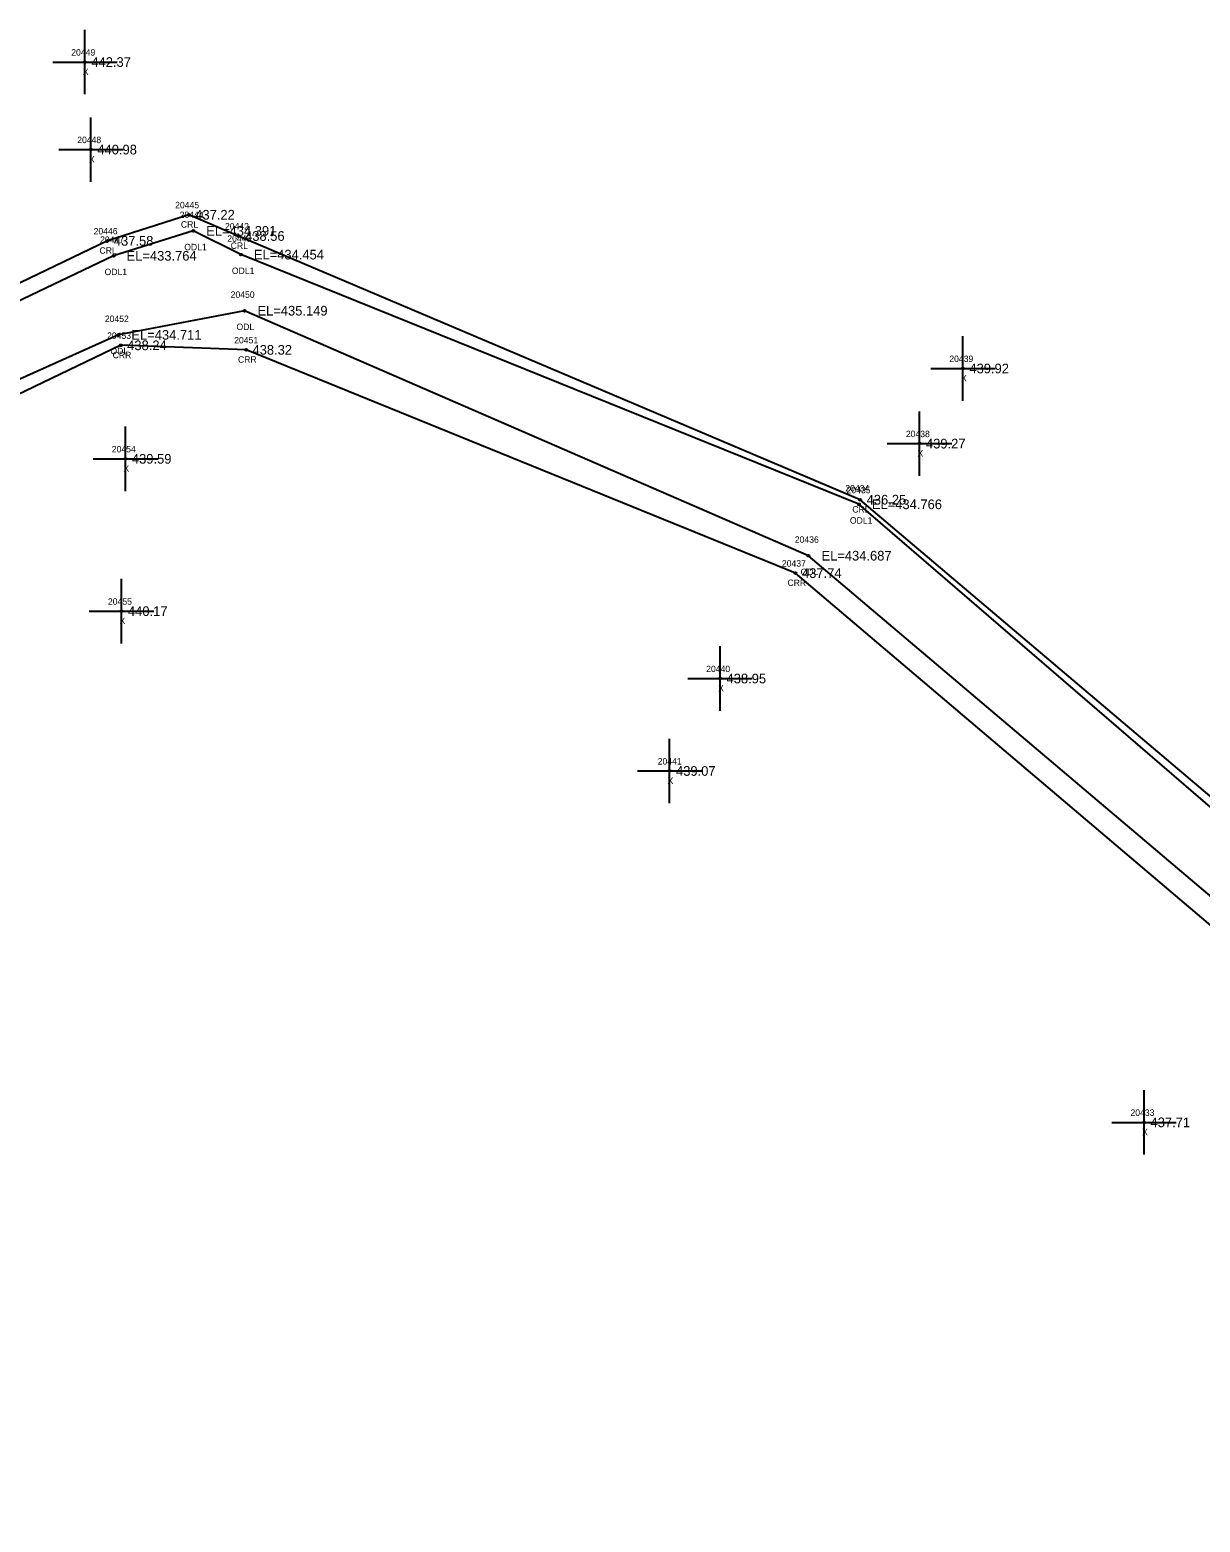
# Model space of a CAD drawing. Extents: x 1763022 to 1764007, y 824123 to 825394.
# Drawn here: x 1763194.4 to 1763375.9, y 824815.6 to 825047.2 of the extents above; entities that cross this region are included whole.
import ezdxf

# ---------------------------------------------------------------- set-up
doc = ezdxf.new("R2010")
doc.units = 0
for name, color, linetype in [('RD_EX_H2O', 7, 'Continuous'), ('RD_EX_H2O_txCode', 7, 'Continuous'), ('RD_EX_Misc', 7, 'Continuous'), ('RD_EX_Misc_txCode', 7, 'Continuous'), ('RD_EX_TX_H2O_ELEV', 7, 'Continuous'), ('RD_EX_TX_Misc_ELEV', 7, 'Continuous'), ('RD_SMD_Locator', 7, 'Continuous')]:
    doc.layers.add(name, color=color, linetype=linetype)

msp = doc.modelspace()

# ---------------------------------------------------------------- linework, layer by layer
at = {"layer": 'RD_EX_H2O'}
for points in [[(1763469.64, 824827.68), (1763444.91, 824845.55), (1763435.48, 824853.42), (1763401.74, 824907.76), (1763323.19, 824974.27), (1763226.75, 825015.18), (1763219.02, 825018.48), (1763206.39, 825014.43), (1763109.02, 824967.64), (1763091.9, 824957.32), (1763081.74, 824947.35), (1763046.14, 824865.15)], [(1763468.68, 824825.92), (1763443.51, 824843.03), (1763433.52, 824852.2), (1763400.31, 824906.96), (1763323, 824973.55), (1763227.11, 825012.29), (1763219.72, 825015.97), (1763207.36, 825012.11), (1763110.44, 824965.8), (1763093.36, 824955.52), (1763084.67, 824946.23), (1763047.83, 824863.38)], [(1763462.4, 824816.93), (1763437.96, 824834.78), (1763425.74, 824848.09), (1763393.61, 824899.16), (1763315.18, 824965.58), (1763227.67, 825003.59), (1763208.11, 824999.84), (1763110.65, 824956.1), (1763090.65, 824936.63), (1763063.26, 824852.64)], [(1763459.77, 824813.09), (1763437.3, 824833.98), (1763421.73, 824846.89), (1763391.2, 824896.67), (1763313.16, 824962.88), (1763227.9, 824997.52), (1763208.46, 824998.22), (1763114.18, 824952.92), (1763092.86, 824935.95), (1763064.35, 824852.13)]]:
    msp.add_lwpolyline(points, dxfattribs=at)
at = {"layer": 'RD_EX_Misc'}
for p, q in [((1763202.9, 825037.17), (1763202.9, 825047.17)), ((1763197.9, 825042.17), (1763207.9, 825042.17)), ((1763203.83, 825023.59), (1763203.83, 825033.59)), ((1763198.83, 825028.59), (1763208.83, 825028.59)), ((1763339.13, 824989.63), (1763339.13, 824999.63)), ((1763334.13, 824994.63), (1763344.13, 824994.63)), ((1763332.39, 824977.97), (1763332.39, 824987.97)), ((1763209.19, 824975.61), (1763209.19, 824985.61)), ((1763327.39, 824982.97), (1763337.39, 824982.97)), ((1763204.19, 824980.61), (1763214.19, 824980.61)), ((1763208.58, 824951.97), (1763208.58, 824961.97)), ((1763203.58, 824956.97), (1763213.58, 824956.97)), ((1763301.45, 824941.52), (1763301.45, 824951.52)), ((1763296.45, 824946.52), (1763306.45, 824946.52)), ((1763293.61, 824927.18), (1763293.61, 824937.18)), ((1763288.61, 824932.18), (1763298.61, 824932.18)), ((1763367.23, 824872.66), (1763367.23, 824882.66)), ((1763362.23, 824877.66), (1763372.23, 824877.66))]:
    msp.add_line(p, q, dxfattribs=at)
at = {"layer": 'RD_SMD_Locator'}
for centre in [(1763202.9, 825042.17), (1763203.83, 825028.59), (1763219.02, 825018.48), (1763219.72, 825015.97), (1763226.75, 825015.18), (1763206.39, 825014.43), (1763207.36, 825012.11), (1763227.11, 825012.29), (1763227.67, 825003.59), (1763208.11, 824999.84), (1763208.46, 824998.22), (1763227.9, 824997.52), (1763339.13, 824994.63), (1763332.39, 824982.97), (1763209.19, 824980.61), (1763323, 824973.55), (1763323.19, 824974.27), (1763315.18, 824965.58), (1763313.16, 824962.88), (1763208.58, 824956.97), (1763301.45, 824946.52), (1763293.61, 824932.18), (1763367.23, 824877.66)]:
    msp.add_circle(centre, 0.15, dxfattribs=at)

# ---------------------------------------------------------------- texts
at = {"layer": 'RD_EX_H2O_txCode'}
for s, p in [('20445', (1763216.9, 825019.48)), ('20444', (1763217.6, 825017.97)), ('CRL', (1763217.79, 825016.48)), ('20442', (1763224.63, 825016.18)), ('20446', (1763204.25, 825015.43)), ('20447', (1763205.25, 825014.11)), ('20443', (1763224.99, 825014.29)), ('CRL', (1763205.16, 825012.43)), ('ODL1', (1763218.31, 825012.97)), ('CRL', (1763225.52, 825013.18)), ('ODL1', (1763205.95, 825009.11)), ('ODL1', (1763225.7, 825009.29)), ('20450', (1763225.51, 825005.59)), ('20452', (1763205.99, 825001.84)), ('ODL', (1763226.42, 825000.59)), ('20453', (1763206.34, 824999.22)), ('20451', (1763226.06, 824998.52)), ('ODL', (1763206.86, 824996.84)), ('CRR', (1763207.2, 824996.22)), ('CRR', (1763226.65, 824995.52)), ('20434', (1763320.88, 824975.55)), ('20435', (1763321.07, 824975.27)), ('CRL', (1763321.96, 824972.27)), ('ODL1', (1763321.59, 824970.55)), ('20436', (1763313.04, 824967.58)), ('20437', (1763311.04, 824963.88)), ('CRR', (1763311.91, 824960.88)), ('ODL', (1763313.94, 824962.58))]:
    msp.add_text(s, height=1, dxfattribs=at).set_placement(p)
at = {"layer": 'RD_EX_Misc_txCode'}
for s, p in [('20449', (1763200.78, 825043.17)), ('X', (1763202.58, 825040.17)), ('20448', (1763201.71, 825029.59)), ('X', (1763203.52, 825026.59)), ('20439', (1763337.01, 824995.63)), ('X', (1763338.82, 824992.63)), ('20438', (1763330.27, 824983.97)), ('20454', (1763207.07, 824981.61)), ('X', (1763332.07, 824980.97)), ('X', (1763208.88, 824978.61)), ('20455', (1763206.47, 824957.97)), ('X', (1763208.27, 824954.97)), ('20440', (1763299.29, 824947.52)), ('X', (1763301.14, 824944.52)), ('20441', (1763291.77, 824933.18)), ('X', (1763293.29, 824930.18)), ('20433', (1763365.12, 824878.66)), ('X', (1763366.92, 824875.66))]:
    msp.add_text(s, height=1, dxfattribs=at).set_placement(p)
at = {"layer": 'RD_EX_TX_H2O_ELEV'}
for s, p in [('437.22', (1763220.02, 825017.73)), ('437.58', (1763207.39, 825013.68)), ('EL=434.391', (1763221.72, 825015.22)), ('438.56', (1763227.75, 825014.43)), ('EL=433.764', (1763209.36, 825011.36)), ('EL=434.454', (1763229.11, 825011.54)), ('EL=435.149', (1763229.67, 825002.84)), ('438.24', (1763209.46, 824997.47)), ('EL=434.711', (1763210.11, 824999.09)), ('438.32', (1763228.9, 824996.77)), ('436.25', (1763324.19, 824973.52)), ('EL=434.766', (1763325, 824972.8)), ('EL=434.687', (1763317.18, 824964.83)), ('437.74', (1763314.16, 824962.13))]:
    msp.add_text(s, height=1.5, dxfattribs=at).set_placement(p)
at = {"layer": 'RD_EX_TX_Misc_ELEV'}
for s, p in [('442.37', (1763203.9, 825041.42)), ('440.98', (1763204.83, 825027.84)), ('439.92', (1763340.13, 824993.88)), ('439.27', (1763333.39, 824982.22)), ('439.59', (1763210.19, 824979.86)), ('440.17', (1763209.58, 824956.22)), ('438.95', (1763302.45, 824945.77)), ('439.07', (1763294.61, 824931.43)), ('437.71', (1763368.23, 824876.91))]:
    msp.add_text(s, height=1.5, dxfattribs=at).set_placement(p)

doc.saveas('drawing.dxf')
